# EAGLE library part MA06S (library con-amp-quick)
AMP QUICK CONNECTOR
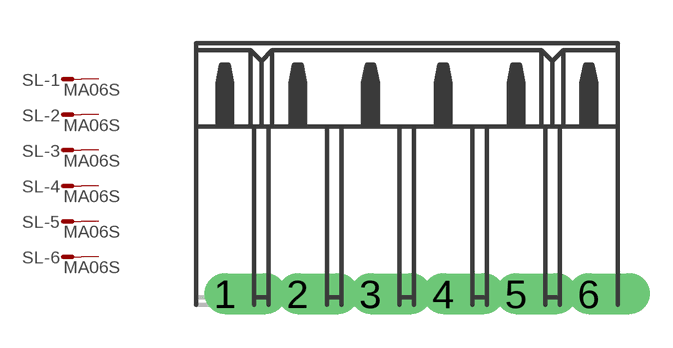
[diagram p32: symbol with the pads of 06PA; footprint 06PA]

Designator prefix SL; gates -1=M -2=M -3=M -4=M -5=M -6=M

## MA06S  [06PA]
1  -1:S  pas
2  -2:S  pas
3  -3:S  pas
4  -4:S  pas
5  -5:S  pas
6  -6:S  pas

## Footprint 06PA (pad centres in mm)
AMP QUICK CONNECTOR
drill 0.914 offset: 1 -6.35,0; 2 -3.81,0; 3 -1.27,0; 4 1.27,0; 5 3.81,0; 6 6.35,0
